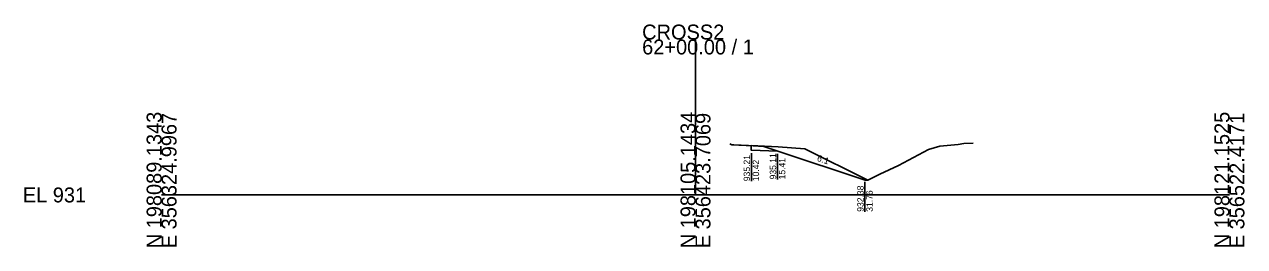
# Model space of a CAD drawing. Extents: x -26 to 203, y -10 to 14021.
# Drawn here: x -25.7 to 202.8, y 2990.3 to 3032 of the extents above; entities that cross this region are included whole.
import ezdxf

# ---------------------------------------------------------------- set-up
doc = ezdxf.new("R2010")
doc.units = 0
for name, color, linetype in [('Default', 7, 'Continuous'), ('P_E_XS_Ground', 7, 'Continuous'), ('P_XS', 7, 'Continuous'), ('P_XS_EAR_CommonGrnd', 7, 'Continuous'), ('P_XS_Lane', 7, 'Continuous'), ('P_XS_Rock', 7, 'Continuous')]:
    doc.layers.add(name, color=color, linetype=linetype)

msp = doc.modelspace()

# ---------------------------------------------------------------- linework, layer by layer
at = {"layer": 'Default'}
for p, q in [((100, 3000), (100, 3029.16)), ((0, 3000), (100, 3000)), ((100, 3000), (200, 3000))]:
    msp.add_line(p, q, dxfattribs=at)
at = {"layer": 'P_E_XS_Ground'}
for p, q in [((106.42, 3009.57), (106.81, 3009.4)), ((106.81, 3009.4), (107.2, 3009.38)), ((107.2, 3009.38), (115.5, 3009.04)), ((115.5, 3009.04), (120.5, 3008.64)), ((120.5, 3008.64), (132.26, 3002.76)), ((138.04, 3005.51), (143.61, 3008.54)), ((143.61, 3008.54), (145.73, 3009.17)), ((145.73, 3009.17), (149.22, 3009.48)), ((149.22, 3009.48), (150.26, 3009.68)), ((150.26, 3009.68), (152.03, 3009.72)), ((134.53, 3003.9), (138.04, 3005.51)), ((134.53, 3003.9), (132.26, 3002.76))]:
    msp.add_line(p, q, dxfattribs=at)
at = {"layer": 'P_XS'}
for p, q in [((106.81, 3009.4), (110.81, 3009.24)), ((110.81, 3009.24), (112.81, 3009.08)), ((115.41, 3008.21), (112.81, 3009.08))]:
    msp.add_line(p, q, dxfattribs=at)
at = {"layer": 'P_XS_EAR_CommonGrnd'}
msp.add_lwpolyline([(110.42, 3009.25), (115.5, 3009.04), (120.5, 3008.64), (132.26, 3002.76), (131.76, 3002.76), (115.41, 3008.21), (110.42, 3008.41)], close=True, dxfattribs=at)
at = {"layer": 'P_XS_Lane'}
for p, q in [((110.42, 3009.25), (110.42, 3008.41)), ((110.42, 3008.41), (115.41, 3008.21)), ((131.76, 3002.76), (115.41, 3008.21)), ((132.26, 3002.76), (131.76, 3002.76))]:
    msp.add_line(p, q, dxfattribs=at)
at = {"layer": 'P_XS_Rock'}
for p, q in [((110.46, 3007.87), (110.46, 3002.58)), ((115.36, 3007.72), (115.36, 3002.91)), ((131.74, 3002.44), (131.74, 2996.85))]:
    msp.add_line(p, q, dxfattribs=at)

# ---------------------------------------------------------------- texts
at = {"layer": 'Default'}
for s, p in [('CROSS2', (90, 3029.16)), ('62+00.00 / 1', (90, 3026.36)), ('EL 931', (-26, 2998.6))]:
    msp.add_text(s, height=2.8, dxfattribs=at).set_placement(p)
for s, p in [('N 198089.1343', (0, 2990)), ('E 356324.9967', (2.8, 2990)), ('N 198105.1434', (100, 2990)), ('E 356423.7069', (102.8, 2990)), ('N 198121.1525', (200, 2990)), ('E 356522.4171', (202.8, 2990))]:
    msp.add_text(s, height=2.8, rotation=90, dxfattribs=at).set_placement(p)
at = {"layer": 'P_XS_Rock'}
for s, rotation, p in [('935.11', 90, (115.11, 3002.92)), ('935.21', 90, (110.21, 3002.58)), ('10.42', 90, (111.91, 3002.58)), ('15.41', 90, (116.81, 3002.92)), ('6:1', 341.5651, (122.66, 3006.42)), ('932.38', 90, (131.49, 2996.85)), ('31.76', 90, (133.19, 2996.85))]:
    msp.add_text(s, height=1.2, rotation=rotation, dxfattribs=at).set_placement(p)

doc.saveas('drawing.dxf')
